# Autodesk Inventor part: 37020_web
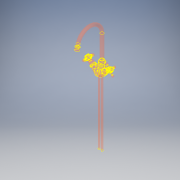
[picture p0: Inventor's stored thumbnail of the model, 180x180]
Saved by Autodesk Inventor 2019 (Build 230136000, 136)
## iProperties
allow_slope_adjustment: 0 ul
connection_type: 14 ul
flow_configuration: 1 ul
flow_direction: 0 ul
loss_method: 0 ul
radius: 5,000 mm
Created: 2018-10
Part Number: 37020_web
Material: Generic
Document SubType Name: Modeling
Designer: jaje1
Density: 1 g/cm^3
Appearance: Default
cw_connection: 0:0:1 ul
cwfu: 0:0:
description: 0:0:
hw_connection: 0:0:1 ul
hwfu: 0:0:
manufacturer: 0:0:
model: 0:0:
url: 0:0:
vent_connection: 0:0:
waste_connection: 0:0:
wfu: 0:0:
Sending System: CREO PARAMETRIC BY PTC INC, 2017380
Preprocessor: CREO PARAMETRIC BY PTC INC, 2017380
Title: 37020_WEB
Author: jaj
Revision Number: 1LAST_VERSION
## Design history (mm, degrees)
node "37020_web.stp"
feature "Surface1"
body "Srf1"
feature "Surface2"
body "Srf2"
feature "Surface3"
body "Srf3"
feature "Surface4"
body "Srf4"
feature "Surface5"
body "Srf5"
feature "Surface6"
body "Srf6"
feature "Surface7"
body "Srf7"
feature "Surface8"
body "Srf8"
feature "Surface9"
body "Srf9"
feature "Surface10"
body "Srf10"
feature "Surface11"
body "Srf11"
